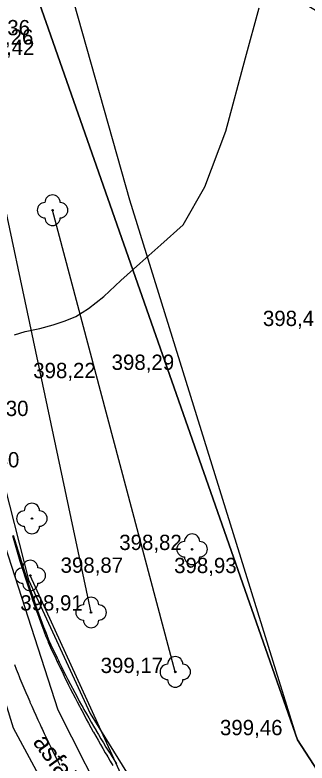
# Model space of a CAD drawing. Extents: x -574342 to -508101, y -1143544 to -1123894.
# Drawn here: x -508415.22 to -508396.11, y -1143308.19 to -1143259.23 of the extents above; entities that cross this region are included whole.
import ezdxf

# ---------------------------------------------------------------- set-up
doc = ezdxf.new("R2010")
doc.units = 0
for name, color, linetype in [('01_PARCELY_NAVRH_PC', 7, 'Continuous'), ('01_PARCELY_NAVRH_ZPF', 7, 'Continuous'), ('01_PARCELY_NAVRH_ŽP', 7, 'Continuous'), ('1000', 7, 'Continuous'), ('15', 7, 'Continuous'), ('21', 7, 'Continuous'), ('37', 7, 'Continuous'), ('42', 7, 'Continuous'), ('54', 7, 'Continuous'), ('55', 7, 'Continuous'), ('cesty', 7, 'Continuous'), ('Level 255', 7, 'Continuous'), ('VRST VEDL', 7, 'Continuous')]:
    doc.layers.add(name, color=color, linetype=linetype)

msp = doc.modelspace()

# ---------------------------------------------------------------- linework, layer by layer
at = {"layer": '01_PARCELY_NAVRH_PC'}
msp.add_lwpolyline([(-508451.57, -1143168.14), (-508437.66, -1143207.58), (-508425.52, -1143241.92), (-508422.7, -1143249.88), (-508420.08, -1143265.35), (-508416.18, -1143288.91), (-508414.34, -1143296.2), (-508410.3, -1143304.94), (-508406.96, -1143310.33), (-508402.64, -1143313.55), (-508394.5, -1143317.14), (-508397.53, -1143325.93), (-508402.47, -1143323.55), (-508407.39, -1143320.93), (-508414.82, -1143312.69), (-508418.17, -1143303.49), (-508422.28, -1143289.33), (-508426.41, -1143265.09), (-508431, -1143245.85), (-508431.86, -1143242.81), (-508432.73, -1143240.34), (-508445.99, -1143206.42), (-508454.33, -1143183.49)], dxfattribs=at)
at = {"layer": '01_PARCELY_NAVRH_ZPF'}
msp.add_lwpolyline([(-508319.096, -1143395.378), (-508344.92, -1143326.36), (-508356.16, -1143314.16), (-508380.74, -1143302.76), (-508393.61, -1143260.11), (-508401.25, -1143255.47), (-508414.23, -1143256.72), (-508396.73, -1143306.67), (-508393.87, -1143311.09), (-508388.31, -1143315.9), (-508376.72, -1143318.72), (-508368.91, -1143322.84), (-508361.58, -1143328.14), (-508355.53, -1143335.68), (-508351.18, -1143342.58), (-508345.08, -1143368.8), (-508338.96, -1143386.69), (-508322.95, -1143422.01), (-508319.096, -1143425.736)], dxfattribs=at)
at = {"layer": '01_PARCELY_NAVRH_ŽP'}
msp.add_lwpolyline([(-508355.53, -1143335.68), (-508361.58, -1143328.14), (-508368.91, -1143322.84), (-508376.72, -1143318.72), (-508388.31, -1143315.9), (-508393.87, -1143311.09), (-508396.73, -1143306.67), (-508414.23, -1143256.72), (-508419.24, -1143259.91), (-508420.08, -1143265.35), (-508416.18, -1143288.91), (-508414.34, -1143296.2), (-508410.3, -1143304.94), (-508406.96, -1143310.33), (-508402.64, -1143313.55), (-508394.5, -1143317.14), (-508377.05, -1143323.29), (-508363.05, -1143330.55), (-508352.96, -1143343.32)], dxfattribs=at)
at = {"layer": '1000'}
for points in [[(-508415.391, -1143293.301), (-508414.895, -1143294.975), (-508414.361, -1143296.639), (-508414.268, -1143296.915), (-508414.166, -1143297.216), (-508414.063, -1143297.516), (-508413.958, -1143297.816), (-508413.852, -1143298.115), (-508413.79, -1143298.289), (-508413.745, -1143298.413), (-508413.637, -1143298.712), (-508413.528, -1143299.01), (-508413.417, -1143299.307), (-508413.305, -1143299.604), (-508413.192, -1143299.9), (-508413.182, -1143299.927), (-508413.077, -1143300.197), (-508413.043, -1143300.285), (-508412.951, -1143300.488), (-508412.819, -1143300.777), (-508412.686, -1143301.065), (-508412.552, -1143301.353), (-508412.471, -1143301.523), (-508412.416, -1143301.64), (-508412.28, -1143301.927), (-508412.142, -1143302.212), (-508412.003, -1143302.498), (-508411.863, -1143302.782), (-508411.722, -1143303.066), (-508411.708, -1143303.094), (-508411.579, -1143303.35), (-508411.436, -1143303.632), (-508411.291, -1143303.914), (-508411.145, -1143304.196), (-508410.999, -1143304.476), (-508410.91, -1143304.645), (-508410.851, -1143304.757), (-508410.702, -1143305.036), (-508410.551, -1143305.315), (-508410.4, -1143305.593), (-508410.248, -1143305.87), (-508410.094, -1143306.147), (-508410.078, -1143306.176), (-508409.939, -1143306.423), (-508409.784, -1143306.698), (-508409.627, -1143306.972), (-508409.469, -1143307.246), (-508409.31, -1143307.52), (-508409.212, -1143307.686), (-508409.148, -1143307.796), (-508408.982, -1143308.08), (-508408.816, -1143308.363)], [(-508415.33, -1143293.283), (-508414.817, -1143294.951), (-508414.292, -1143296.615), (-508414.2, -1143296.893), (-508414.098, -1143297.193), (-508413.995, -1143297.492), (-508413.89, -1143297.792), (-508413.783, -1143298.09), (-508413.721, -1143298.264), (-508413.676, -1143298.388), (-508413.566, -1143298.686), (-508413.456, -1143298.983), (-508413.344, -1143299.28), (-508413.23, -1143299.576), (-508413.116, -1143299.871), (-508413.105, -1143299.897), (-508413, -1143300.166), (-508412.964, -1143300.255), (-508412.871, -1143300.456), (-508412.736, -1143300.744), (-508412.599, -1143301.03), (-508412.462, -1143301.316), (-508412.379, -1143301.485), (-508412.323, -1143301.601), (-508412.182, -1143301.886), (-508412.04, -1143302.17), (-508411.897, -1143302.453), (-508411.753, -1143302.735), (-508411.607, -1143303.016), (-508411.593, -1143303.044), (-508411.46, -1143303.297), (-508411.311, -1143303.577), (-508411.161, -1143303.856), (-508411.01, -1143304.134), (-508410.858, -1143304.412), (-508410.765, -1143304.578), (-508410.704, -1143304.688), (-508410.549, -1143304.964), (-508410.393, -1143305.239), (-508410.235, -1143305.513), (-508410.076, -1143305.787), (-508409.916, -1143306.059), (-508409.899, -1143306.088), (-508409.755, -1143306.331), (-508409.595, -1143306.603), (-508409.433, -1143306.874), (-508409.27, -1143307.144), (-508409.105, -1143307.414), (-508409, -1143307.576), (-508408.931, -1143307.683), (-508408.751, -1143307.96), (-508408.572, -1143308.236)]]:
    msp.add_lwpolyline(points, dxfattribs=at)
at = {"layer": '21'}
msp.add_lwpolyline([(-508415.261, -1143301.749), (-508415.139, -1143302.053), (-508415.015, -1143302.357), (-508414.942, -1143302.537), (-508414.891, -1143302.661), (-508414.765, -1143302.964), (-508414.638, -1143303.266), (-508414.51, -1143303.568), (-508414.381, -1143303.87), (-508414.25, -1143304.17), (-508414.237, -1143304.2), (-508414.118, -1143304.471), (-508413.985, -1143304.771), (-508413.851, -1143305.07), (-508413.715, -1143305.368), (-508413.578, -1143305.667), (-508413.495, -1143305.846), (-508413.44, -1143305.964), (-508413.301, -1143306.261), (-508413.161, -1143306.558), (-508413.019, -1143306.853), (-508412.876, -1143307.149), (-508412.732, -1143307.443), (-508412.717, -1143307.475), (-508412.587, -1143307.737), (-508412.44, -1143308.031), (-508412.293, -1143308.324)], dxfattribs=at)
at = {"layer": '37'}
for points in [[(-508473.82, -1143129.8), (-508468.34, -1143141.31), (-508458.53, -1143158.76), (-508453.13, -1143170.86), (-508439.96, -1143210.5), (-508427.56, -1143241.73), (-508421.57, -1143265.72), (-508416.35, -1143292.6), (-508412.42, -1143304.7), (-508408.82, -1143311.83)], [(-508473.82, -1143129.8), (-508468.34, -1143141.31), (-508458.53, -1143158.76), (-508453.13, -1143170.86), (-508439.96, -1143210.5), (-508427.56, -1143241.73), (-508421.57, -1143265.72), (-508416.35, -1143292.6), (-508412.42, -1143304.7), (-508408.82, -1143311.83)], [(-508408.82, -1143311.83), (-508404.37, -1143317.04), (-508398.21, -1143321.18), (-508393.66, -1143322.44), (-508393.79, -1143324.58), (-508400.56, -1143323.11), (-508406.32, -1143319.06), (-508411.41, -1143313.16), (-508415.31, -1143305.9), (-508419.33, -1143292.88), (-508424.96, -1143264.72), (-508428.49, -1143248.11), (-508430.27, -1143242.09), (-508442.28, -1143211.48), (-508455.59, -1143171.17), (-508460.82, -1143160.05), (-508470.5, -1143142.85)], [(-508408.82, -1143311.83), (-508404.37, -1143317.04), (-508398.21, -1143321.18), (-508393.66, -1143322.44), (-508393.79, -1143324.58), (-508400.56, -1143323.11), (-508406.32, -1143319.06), (-508411.41, -1143313.16), (-508415.31, -1143305.9), (-508419.33, -1143292.88), (-508424.96, -1143264.72), (-508428.49, -1143248.11), (-508430.27, -1143242.09), (-508442.28, -1143211.48), (-508455.59, -1143171.17), (-508460.82, -1143160.05), (-508470.5, -1143142.85)]]:
    msp.add_lwpolyline(points, dxfattribs=at)
at = {"layer": '42'}
msp.add_lwpolyline([(-508320.88, -1143423.96), (-508327.62, -1143411.06), (-508338.78, -1143387.2), (-508344.67, -1143370.01), (-508350.79, -1143346.58), (-508354.96, -1143336.71), (-508361.36, -1143329.02), (-508368.91, -1143322.84), (-508376.72, -1143318.72), (-508388.31, -1143315.9), (-508393.87, -1143311.09), (-508396.73, -1143306.67), (-508407.7, -1143271.35), (-508414.18, -1143248.41), (-508420.68, -1143216.75), (-508423.64, -1143189.02), (-508427.95, -1143159.6), (-508434.68, -1143117.69), (-508435.012, -1143116.058)], dxfattribs=at)
msp.add_lwpolyline([(-508320.88, -1143423.96), (-508327.62, -1143411.06), (-508338.78, -1143387.2), (-508344.67, -1143370.01), (-508350.79, -1143346.58), (-508354.96, -1143336.71), (-508361.36, -1143329.02), (-508368.91, -1143322.84), (-508376.72, -1143318.72), (-508388.31, -1143315.9), (-508393.87, -1143311.09), (-508396.73, -1143306.67), (-508407.7, -1143271.35), (-508414.18, -1143248.41), (-508420.68, -1143216.75), (-508423.64, -1143189.02), (-508427.95, -1143159.6), (-508434.68, -1143117.69), (-508435.012, -1143116.058)], dxfattribs=at)
at = {"layer": '54'}
for centre in [(-508412.76, -1143272.01), (-508414.11, -1143292.19), (-508403.63, -1143294.2), (-508414.22, -1143295.92), (-508410.24, -1143298.34), (-508404.73, -1143302.23)]:
    msp.add_circle(centre, 0.05, dxfattribs=at)
for centre, start, end in [((-508412.76, -1143271.51), 0, 180), ((-508413.26, -1143272.01), 90, 270), ((-508412.26, -1143272.01), 270, 90), ((-508412.76, -1143272.51), 180, 0), ((-508414.11, -1143291.69), 0, 180), ((-508414.61, -1143292.19), 90, 270), ((-508413.61, -1143292.19), 270, 90), ((-508414.11, -1143292.69), 180, 0), ((-508403.63, -1143293.7), 0, 180), ((-508404.13, -1143294.2), 90, 270), ((-508403.13, -1143294.2), 270, 90), ((-508403.63, -1143294.7), 180, 0), ((-508414.22, -1143295.42), 0, 180), ((-508414.72, -1143295.92), 90, 270), ((-508413.72, -1143295.92), 270, 90), ((-508414.22, -1143296.42), 180, 0), ((-508410.24, -1143297.84), 0, 180), ((-508410.74, -1143298.34), 90, 270), ((-508409.74, -1143298.34), 270, 90), ((-508410.24, -1143298.84), 180, 0), ((-508404.73, -1143301.73), 0, 180), ((-508405.23, -1143302.23), 90, 270), ((-508404.23, -1143302.23), 270, 90), ((-508404.73, -1143302.73), 180, 0)]:
    msp.add_arc(centre, 0.5, start, end, dxfattribs=at)
at = {"layer": '55'}
msp.add_line((-508404.73, -1143302.23), (-508412.76, -1143272.01), dxfattribs=at)
msp.add_line((-508404.73, -1143302.23), (-508412.76, -1143272.01), dxfattribs=at)
for points in [[(-508410.24, -1143298.34), (-508420.04, -1143252.1), (-508438.58, -1143205.02)], [(-508410.24, -1143298.34), (-508420.04, -1143252.1), (-508438.58, -1143205.02)], [(-508399.15, -1143318.4), (-508408.17, -1143309.19), (-508414.22, -1143295.92)], [(-508399.15, -1143318.4), (-508408.17, -1143309.19), (-508414.22, -1143295.92)]]:
    msp.add_lwpolyline(points, dxfattribs=at)
at = {"layer": 'cesty'}
for centre, start, end in [((-508399.986, -1143262.414), 16.4935, 95.3361), ((-508413.198, -1143263.648), 95.3361, 192.4584)]:
    msp.add_arc(centre, 7.5, start, end, dxfattribs=at)
at = {"layer": 'VRST VEDL'}
msp.add_lwpolyline([(-508415.24, -1143280.162), (-508414.545, -1143279.947), (-508413.59, -1143279.741), (-508412.721, -1143279.509), (-508411.938, -1143279.251), (-508411.241, -1143278.968), (-508410.399, -1143278.435), (-508409.414, -1143277.652), (-508408.285, -1143276.62), (-508407.041, -1143275.493), (-508405.682, -1143274.273), (-508404.207, -1143272.959), (-508402.79, -1143270.483), (-508401.43, -1143266.845), (-508400.128, -1143262.046), (-508399.246, -1143258.76)], dxfattribs=at)

# ---------------------------------------------------------------- texts
at = {"layer": '15'}
msp.add_text('asfaltová cesta', height=1.2, rotation=305.8449, dxfattribs=at).set_placement((-508414.093, -1143306.831))
msp.add_text('asfaltová cesta', height=1.2, rotation=305.8449, dxfattribs=at).set_placement((-508414.093, -1143306.831))
at = {"layer": 'Level 255'}
for s, p in [('397,36', (-508418.325, -1143260.56)), ('397,26', (-508418.105, -1143261.17)), ('397,42', (-508418.035, -1143261.84)), ('398,47', (-508398.995, -1143279.59)), ('398,29', (-508408.895, -1143282.46)), ('398,22', (-508414.025, -1143283)), ('398,30', (-508418.425, -1143285.48)), ('398,40', (-508419.025, -1143288.84)), ('398,82', (-508408.395, -1143294.25)), ('398,87', (-508412.235, -1143295.74)), ('398,93', (-508404.805, -1143295.76)), ('398,91', (-508414.875, -1143298.21)), ('399,17', (-508409.615, -1143302.3)), ('399,46', (-508401.805, -1143306.37))]:
    msp.add_text(s, height=1, dxfattribs=at).set_placement(p)

doc.saveas('drawing.dxf')
